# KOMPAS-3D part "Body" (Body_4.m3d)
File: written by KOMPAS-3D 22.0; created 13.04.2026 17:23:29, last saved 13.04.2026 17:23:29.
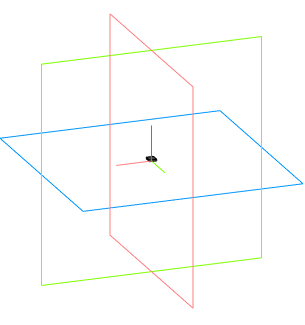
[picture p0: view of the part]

Document properties: Автор: Andrey; Полное имя файла: C:\Users\User1\Documents\Body_4.m3d

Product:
- Part/product: Body

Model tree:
1. Операция без истории:1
